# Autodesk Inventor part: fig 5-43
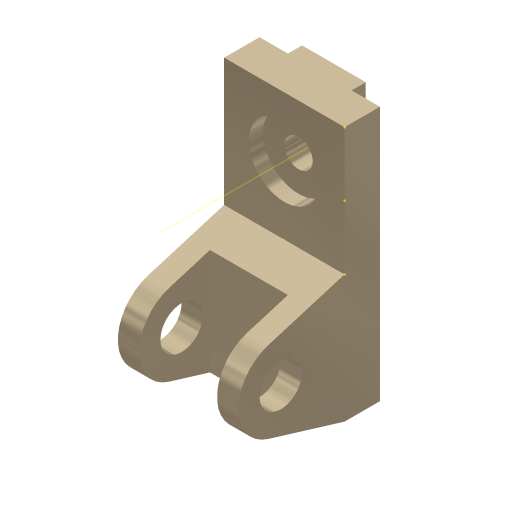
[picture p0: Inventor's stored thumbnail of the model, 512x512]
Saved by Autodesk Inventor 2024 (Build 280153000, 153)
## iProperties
Shininess: 65.0
Angle Display Precision: 2
Document Length Units: 11269
Document Angle Units: 11279
Document Time Units: 11290
Document Mass Units: 11283
Document Length Units Precision: 3
Document Angle Units Precision: 2
Created: 2001-11
Part Number: fig 5-43
Document SubType Name: Modeling
Designer: Renu Muthoo
Density: 1 g/cm^3
Material: Generic
Appearance: Metal-Titanium (Polished)
Density: 0.0
Volumn: 0.0
Area: 0.0
PropertySet Name: Model Information
Control State: 0
Master: False
Checked Out: False
Author: Renu Muthoo
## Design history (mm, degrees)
sketch "Sketch2"
  geometry: L1 (33.257, 104.664)-(33.257, -75.336); L2 (33.257, -75.336)-(8.257, -75.336); L3 (8.257, -75.336)-(-45.451, -59.045); L4 (-45.451, -1.628)-(8.257, 14.664); L5 (8.257, 14.664)-(8.257, 104.664); L6 (8.257, 104.664)-(33.257, 104.664); C1 r 15 at (-36.743, -30.336); A1 r 30 centre (-36.743, -30.336) between (-45.451, -1.628) and (-45.451, -59.045)
  constraints: 12 end point, 2 centre point, 2 equal length, 2 parallel, 2 point on circle, 2 tangent, 1 coincident, 1 perpendicular, 1 vertical
  dimensions: "d0" = 180 distance of L1.start L1.end; "d1" = 30 radius of A1; "d2" = 25 distance of L5.end L1.start; "d3" = 45 distance from line of L2 A1.centre; "d4" = 70 distance from line of L1 A1.centre; "d5" = 30 diameter of C1
extrude "Extrusion1" new body sketch "Sketch2" distance "d6" = 85; taper "d7" = 0 deg
workplane "Work Plane1"
sketch "Sketch3"
  geometry: L1 (15, 62.364)-(70, 62.364); L2 (70, 62.364)-(70, -52.386); L3 (70, -52.386)-(15, -52.386); L4 (15, -52.386)-(15, 62.364); L5 (0, -45)-(0, -28.708) reference
  constraints: 8 end point, 2 parallel, 1 horizontal, 1 perpendicular
  dimensions: "d8" = 55 distance of L1.start L1.end; "d9" = 15 distance between parallel lines of L5 L4
extrude "Extrusion2" cut sketch "Sketch3" distance "d10" = 50; taper "d11" = 0 deg
sketch "Sketch4"
  geometry: L1 (0, 25)-(85, 25) reference; L2 (0, 0)-(0, 25) reference; L3 (20, 25)-(65, 25); L4 (65, 25)-(65, 35); L5 (65, 35)-(20, 35); L6 (20, 35)-(20, 25)
  constraints: 8 end point, 2 parallel, 1 horizontal, 1 perpendicular, 1 point on line
  dimensions: "d12" = 45 distance of L4.end L5.end; "d13" = 10 distance of L3.end L4.end; "d14" = 20 distance between parallel lines of L2 L6
extrude "Extrusion3" join sketch "Sketch4" stored distance "d15" = 50; taper "d16" = 0 deg
sketch "Sketch5"
  geometry: L1 (85, 0)-(85, 90) reference; L2 (0, 90)-(85, 90) reference; 1 further point
  dimensions: "d17" = 42 distance from line of L2 point (42.5, 48); "d18" = 42.5 distance from line of L1 point (42.5, 48)
hole "Hole1" sketch "Sketch5" diameter "d19" = 20; stored, may be unused: countersink angle "d23" = 82 deg, drill point angle "d25" = 118 deg; dims "d20" = 6, "d21" = 50, "d22" = 10, "d24" = 8
workpoint "Work Point1"
workpoint "Work Point2"
workpoint "Work Point3"
workpoint "Work Point4"
workaxis "Work Axis2"
body "Solid1"
node "Sketch1"
